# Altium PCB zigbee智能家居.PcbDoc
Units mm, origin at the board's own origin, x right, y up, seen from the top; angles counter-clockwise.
Board outline 97 x 70 mm, 2 copper layers (Top Layer, Bottom Layer); 56 components, 64 nets, 275 pads, 46 vias.
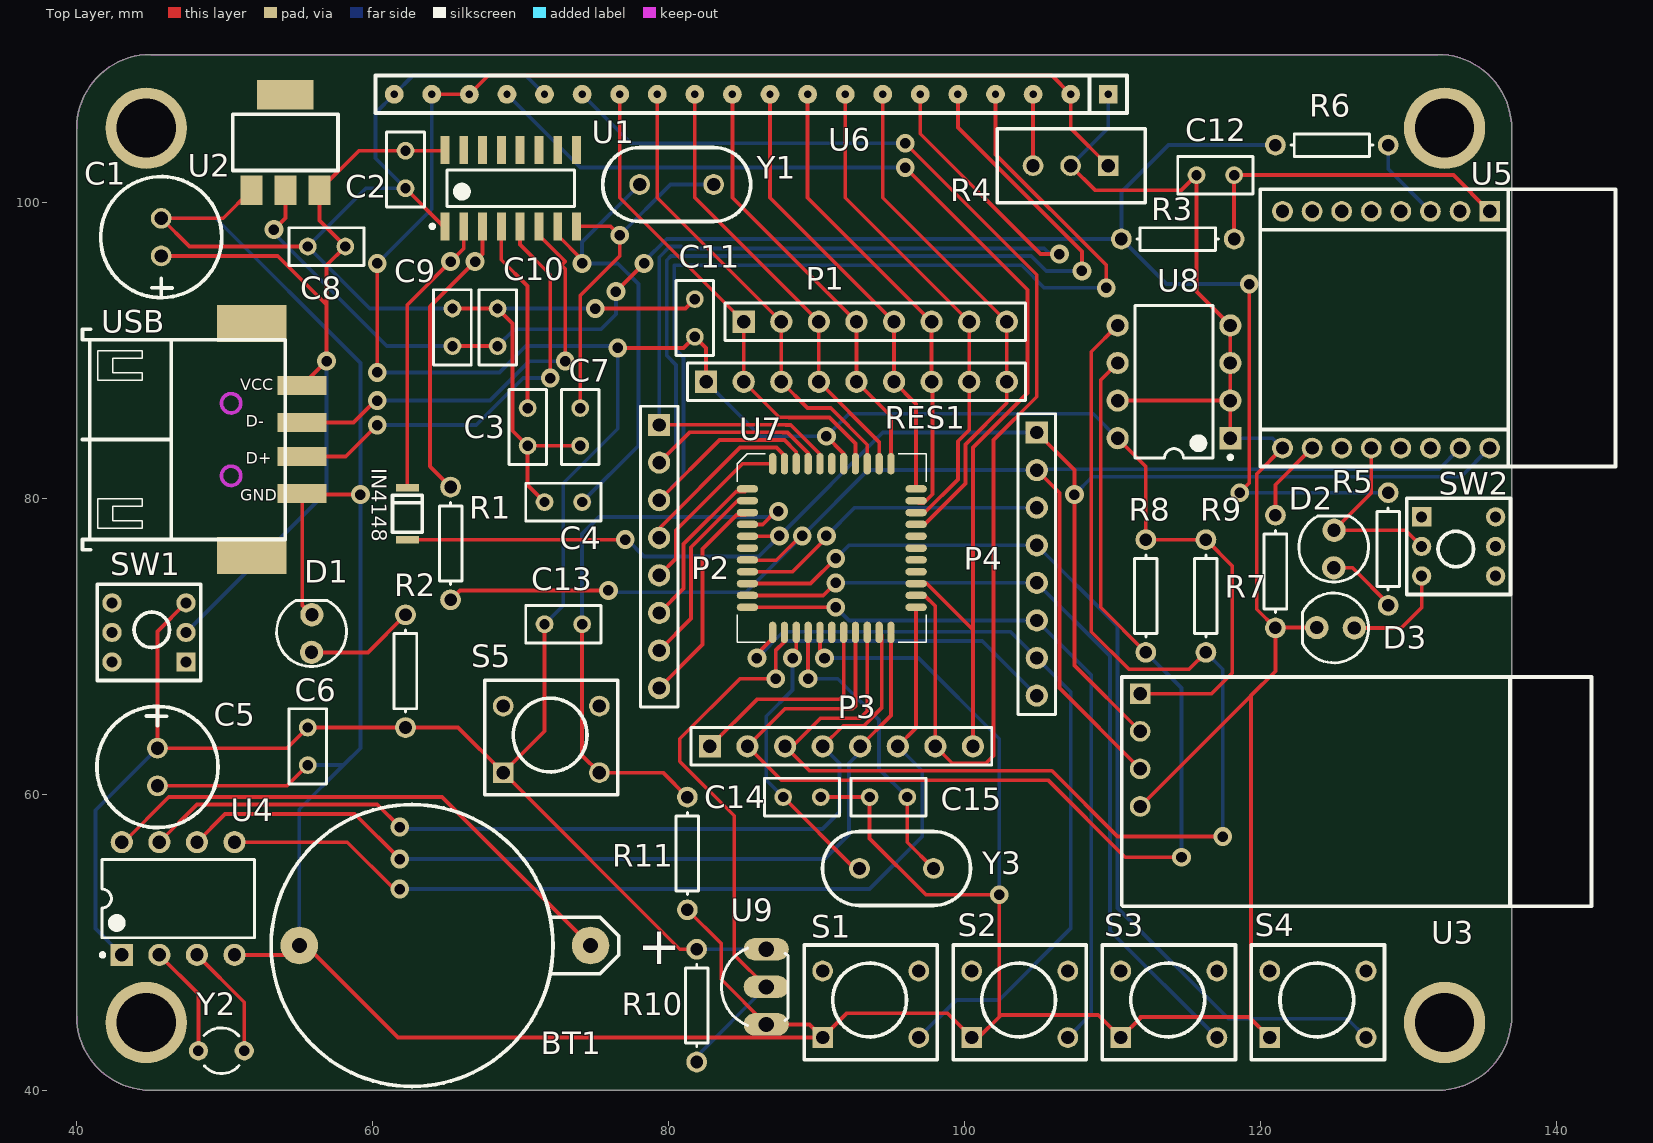
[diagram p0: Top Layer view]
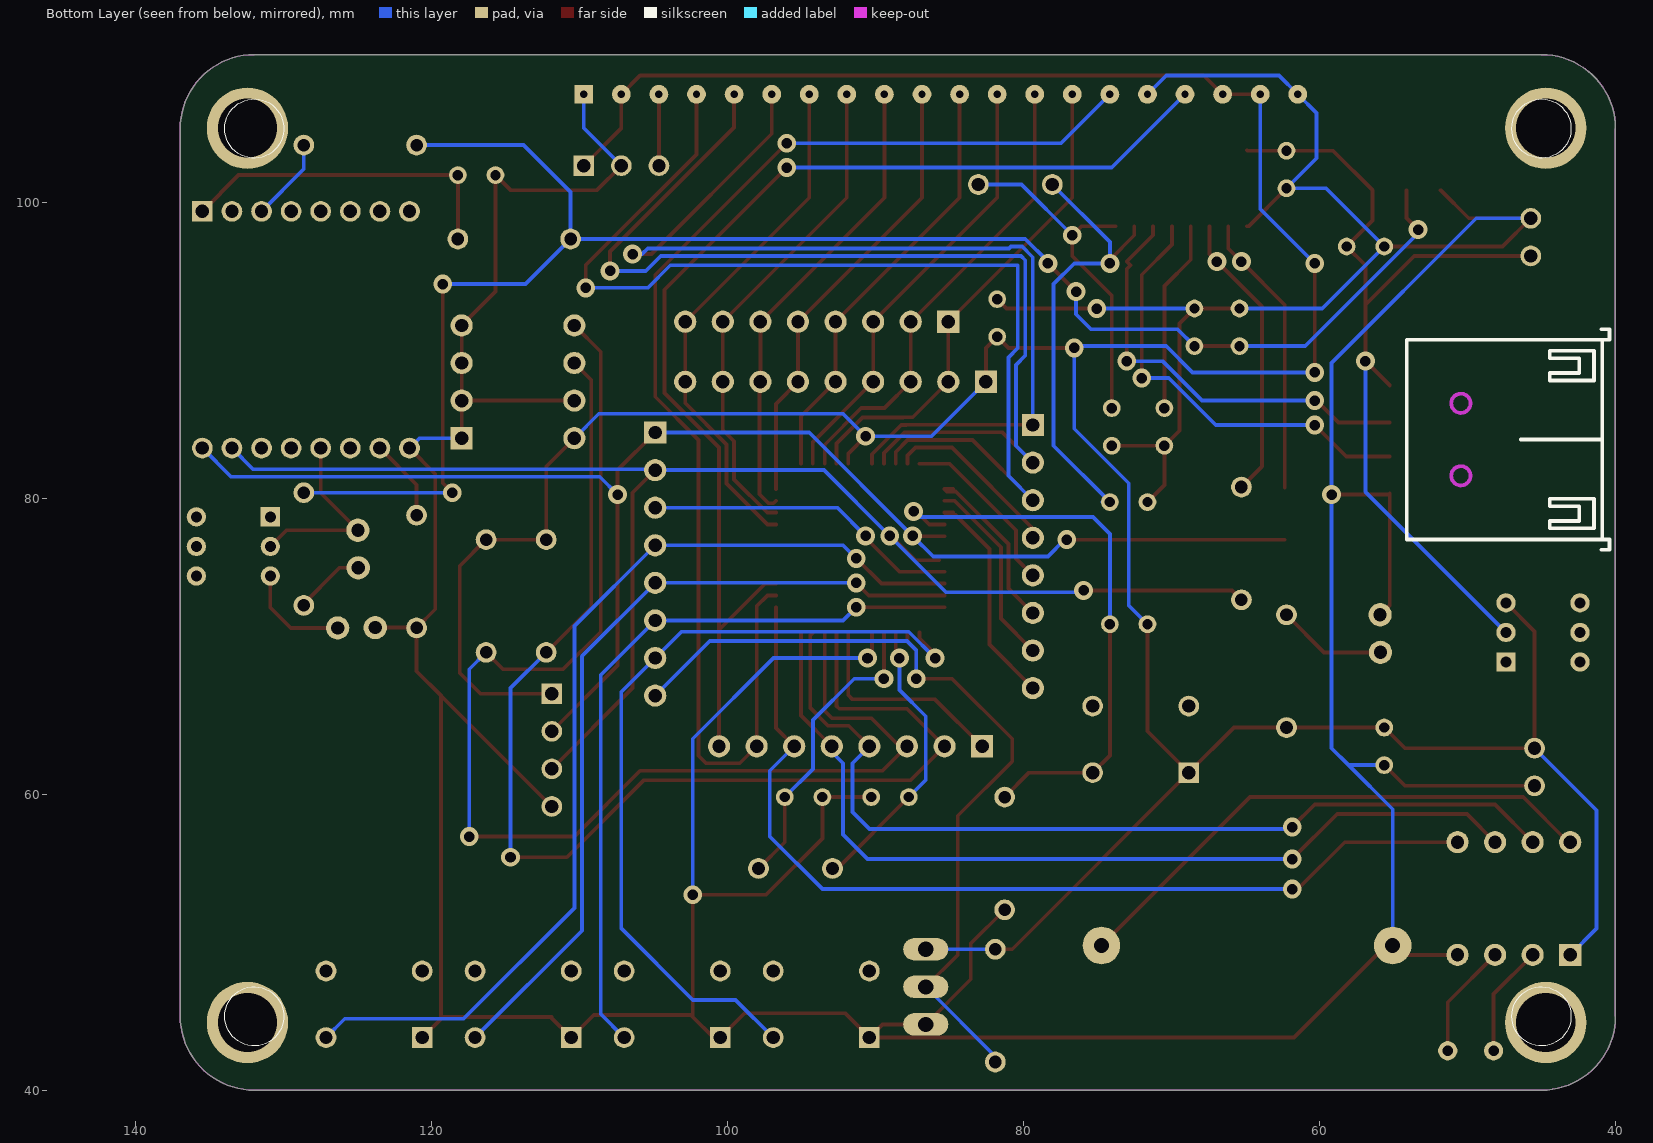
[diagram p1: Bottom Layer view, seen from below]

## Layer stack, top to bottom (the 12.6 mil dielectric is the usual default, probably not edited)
Top Solder: solder mask 0.0102, Solder Resist, Dk 3.5
Top Layer: signal copper 0.0356
Dielectric 1: dielectric 0.32, FR-4, Dk 4.8
Bottom Layer: signal copper 0.0356
Bottom Solder: solder mask 0.0102, Solder Resist, Dk 3.5

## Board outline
40,45 40,105 cw(c45,105) 45,110 132,110 cw(c132,105) 137,105 137,45 cw(c132,45) 132,40 45,40 cw(c45,45)

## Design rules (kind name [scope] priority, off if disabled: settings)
Clearance [All] p1: gap=0.254
HoleSize [All] p1 off: absolutevalues=TRUE maxlimit=2.54 minlimit=0.025 maxpercent=80.000 minpercent=20.000
MinimumSolderMaskSliver MinimumSolderMaskSliver_1 [All] p1: minsoldermaskwidth=0
PolygonConnect [All] p1: connectstyle=Relief reliefconductorwidth=0.254 reliefentries=4 polygonreliefangle="90 Angle" airgapwidth=0.254
RoutingVias [All] p1: holewidth=0.711 width=1.27 viastyle="Through Hole" minholewidth=0.711 minwidth=1.27 maxholewidth=0.711 maxwidth=1.27
SilkToSilkClearance [All] p1 off: silktosilkclearance=0.254
SilkToSolderMaskClearance [IsPad] p1 off: minsilkscreentomaskgap=0.1 clearancetoexposedcopper=TRUE
SolderMaskExpansion [All] p1: expansion=0.102
Width [All] p1: maxlimit=0.254 minlimit=0.254 preferedwidth=0.254
26 further rules are at their usual default settings.

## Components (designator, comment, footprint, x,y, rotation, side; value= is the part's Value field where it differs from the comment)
BT1 "Battery" BATTERY 64.897,49.784 r180 top
C1 "Cap Pol1" "8mm Cap+" 45.974,110.363 r270 top
C2 "Cap" RAD-0.1 62.23,102.235 r90 top
C3 "Cap" RAD-0.1 70.485,84.836 r90 top
C4 "Cap" RAD-0.1 72.898,79.756 r0 top
C5 "Cap Pol1" "8mm Cap+" 45.212,49.149 r90 top
C6 "Cap" RAD-0.1 55.626,63.246 r90 top
C7 "Cap" RAD-0.1 74.041,84.836 r90 top
C8 "Cap" RAD-0.1 56.896,97.028 r180 top
C9 "Cap" RAD-0.1 65.405,91.567 r90 top
C10 "Cap" RAD-0.1 68.453,91.567 r90 top
C11 "Cap" RAD-0.1 81.788,92.202 r90 top
C12 "Cap" RAD-0.1 116.967,101.854 r180 top
C13 "Cap" RAD-0.1 72.898,71.501 r180 top
C14 "Cap" RAD-0.1 94.869,59.817 r0 top
C15 "Cap" RAD-0.1 89.027,59.817 r180 top
D1 "LED3" LED 55.88,72.136 r270 top
D2 "LED3" LED 124.968,77.851 r270 top
D3 "LED3" LED 123.825,71.247 r0 top
IN4148 "IN4148" LL-34 62.357,77.216 r90 top
P1 "Header 8" HDR1X8 85.09,91.948 r0 top
P2 "Header 8" HDR1X8 79.375,84.963 r270 top
P3 "Header 8" HDR1X8 82.804,63.246 r0 top
P4 "Header 8" HDR1X8 104.902,84.455 r270 top
R1 "Res1" AXIAL-0.3 65.278,76.962 r90 top
R2 "Res1" AXIAL-0.3 62.23,68.326 r90 top
R3 "Res1" AXIAL-0.3 114.427,97.536 r180 top
R4 "Res Tap" 变位器 109.728,102.489 r180 top
R5 "Res1" AXIAL-0.3 128.651,76.581 r90 top
R6 "Res1" AXIAL-0.3 124.841,103.886 r0 top
R7 "Res1" AXIAL-0.3 121.031,75.057 r270 top
R8 "Res1" AXIAL-0.3 112.268,73.406 r90 top
R9 "Res1" AXIAL-0.3 116.332,73.406 r90 top
R10 "Res1" AXIAL-0.3 81.915,45.72 r90 top
R11 "Res1" AXIAL-0.3 81.28,56.007 r90 top
RES1 "10K" HDR1X9 82.55,87.884 r0 top
S1 "SW-PB" 6x6四脚开关 90.424,43.561 r0 top
S2 "SW-PB" 6x6四脚开关 100.499,43.561 r0 top
S3 "SW-PB" 6x6四脚开关 110.575,43.561 r0 top
S4 "SW-PB" 6x6四脚开关 120.65,43.561 r0 top
S5 "SW-PB" 6x6四脚开关 68.834,61.468 r0 top
SW1 "Component_1" 6x6六脚开关 48.895,67.945 r90 top
SW2 "Component_1" 6x6六脚开关 129.413,79.756 r270 top
U1 "CH340G" SOIC127P600X170-16N 69.342,100.965 r90 top
U2 "AMS1117-3V3" SOT223 51.816,100.838 r0 top
U3 "ZIGBEE" zigbee直插 111.887,59.182 r0 top
U4 "DS1302" DIP-8 46.863,52.959 r90 top
U5 "ESP-12" ESP-12 127.508,97.155 r180 top
U6 "QC12864B" SIP20 109.728,107.315 r180 top
U7 "STC12C5A60S2" LQFP44 85.344,80.645 r0 top
U8 "24C08A" dip-8 114.173,87.884 r180 top
U9 "DS18B20" TO92 86.614,46.99 r90 top
USB "USB" USB-4-A-SMT 55.245,87.63 r0 top (schematic designator *1)
Y1 "12M" 5mm晶振 83.058,101.219 r180 top
Y2 "37.128KHz" R38 49.784,42.672 r90 top
Y3 "12M" 5mm晶振 97.917,54.991 r180 top

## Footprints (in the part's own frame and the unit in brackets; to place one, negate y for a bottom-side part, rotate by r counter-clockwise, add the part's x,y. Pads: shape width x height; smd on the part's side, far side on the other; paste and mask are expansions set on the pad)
5mm晶振 [mm]
  round 1.4 hole 0.9: 1(0,0) 2(5,0)
  silkscreen extent -2.5,-2.5 7.5,2.5
6x6六脚开关 [mm]
  rect 1.3x1.3 hole 0.75: 1(1,1.5)
  round 1.3 hole 0.75: 2(3,1.5) 3(5,1.5) 4(1,6.5) 5(3,6.5) 6(5,6.5)
  silkscreen extent -0.25,0.5 6.25,7.5
6x6四脚开关 [mm]
  rect 1.4x1.4 hole 0.9 paste+4.5: 1(0,0)
  round 1.4 hole 0.9: 2(6.5,0) 3(6.5,4.5) 4(0,4.5)
  silkscreen extent -1.25,-1.5 7.75,6.25
"8mm Cap+" [mm]
  round 1.4 hole 0.9: 1(13.97,-0.254) 2(11.43,-0.254)
  silkscreen extent 8.61,-4.35 16.8,3.84
AXIAL-0.3 [mm] "Axial Device, Thru-Hole; 2 Leads; 0.3 in Pin Spacing"
  round 1.4 hole 0.85: 1(-3.81,0) 2(3.81,0)
  silkscreen extent -2.77,-0.76 2.77,0.76
BATTERY [mil]
  round 100 hole 40: 1(-387.5,0) 2(387.5,0)
  silkscreen extent -462,-375 462,375
DIP-8 [mm] "DIP; 8 Leads; Row Spacing 7.62 mm; Pitch 2.54 mm"
  rect 1.5x1.5 hole 0.9: 1(-3.81,3.81)
  round 1.5 hole 0.9: 2(-3.81,1.27) 3(-3.81,-1.27) 4(-3.81,-3.81) 5(3.81,-3.81) 6(3.81,-1.27) 7(3.81,1.27) 8(3.81,3.81)
  silkscreen extent -3.93,-5.15 2.65,5.23, body extent -3.6,-5.15 3.6,5.15, height 5.08
dip-8 [mm] "DIP; 8 Leads; Row Spacing 7.62 mm; Pitch 2.54 mm"
  rect 1.5x1.5 hole 0.9: 1(-3.81,3.81)
  round 1.5 hole 0.9: 2(-3.81,1.27) 3(-3.81,-1.27) 4(-3.81,-3.81) 5(3.81,-3.81) 6(3.81,-1.27) 7(3.81,1.27) 8(3.81,3.81)
  silkscreen extent -3.94,-5.15 2.65,5.23, body extent -3.6,-5.15 3.6,5.15, height 5.08
ESP-12 [mm]
  rect 1.4x1.4 hole 0.9: 1(-8,-2.25)
  round 1.4 hole 0.9: 2(-6,-2.25) 3(-4,-2.25) 4(-2,-2.25) 5(0,-2.25) 6(2,-2.25) 7(4,-2.25) 8(6,-2.25) 9(6,13.75) 10(4,13.75) 11(2,13.75) 12(0,13.75) 13(-2,13.75) 14(-4,13.75) 15(-6,13.75) 16(-8,13.75)
  silkscreen extent -16.5,-3.75 7.5,15
HDR1X8 [mm] "Connector; Header; 8 Position"
  rect 1.5x1.5 hole 0.9: 1(0,0)
  round 1.5 hole 0.9: 2(2.54,0) 3(5.08,0) 4(7.62,0) 5(10.16,0) 6(12.7,0) 7(15.24,0) 8(17.78,0)
  silkscreen extent -1.27,-1.27 19.05,1.27
HDR1X9 [mm] "Connector; Header; 9 Position"
  rect 1.5x1.5 hole 0.9: 1(0,0)
  round 1.5 hole 0.9: 2(2.54,0) 3(5.08,0) 4(7.62,0) 5(10.16,0) 6(12.7,0) 7(15.24,0) 8(17.78,0) 9(20.32,0)
  silkscreen extent -1.27,-1.27 21.59,1.27
LED [mil]
  round 62 hole 35.43: 1(100,0) 2(0,1)
  silkscreen extent -38,-93 138,93
LL-34 [mm]
  rect 0.5x1.54 smd: 1(0,0) 2(3.5,0)
  silkscreen extent 0.5,-1 3,1
LQFP44 [mm]
  oval 1.45x0.5 smd: 1(0,0) 2(0,-0.8) 3(0,-1.6) 4(0,-2.4) 5(0,-3.2) 6(0,-4) 7(0,-4.8) 8(0,-5.6) 9(0,-6.4) 10(0,-7.2) 11(0,-8) 23(11.4,-8) 24(11.4,-7.2) 25(11.4,-6.4) 26(11.4,-5.6) 27(11.4,-4.8) 28(11.4,-4) 29(11.4,-3.2) 30(11.4,-2.4) 31(11.4,-1.6) 32(11.4,-0.8) 33(11.4,0)
  oval 0.5x1.45 smd: 12(1.7,-9.7) 13(2.5,-9.7) 14(3.3,-9.7) 15(4.1,-9.7) 16(4.9,-9.7) 17(5.7,-9.7) 18(6.5,-9.7) 19(7.3,-9.7) 20(8.1,-9.7) 21(8.9,-9.7) 22(9.7,-9.7) 34(9.7,1.7) 35(8.9,1.7) 36(8.1,1.7) 37(7.3,1.7) 38(6.5,1.7) 39(5.7,1.7) 40(4.9,1.7) 41(4.1,1.7) 42(3.3,1.7) 43(2.5,1.7) 44(1.7,1.7)
  silkscreen extent -0.67,-10.38 12.08,2.37
R38 [mm] "Crystal, Thru-Hole; 2 Leads; Body 3.1 x 8.2 mm (Dia.xH)"
  round 1.3 hole 0.7: 1(0,1.55) 2(0,-1.55)
  silkscreen extent -1.55,-1.19 1.55,1.17
RAD-0.1 [mm] "Radial Cap, Thru-Hole; 2 Leads; 0.1 in Pin Spacing"
  round 1.2 hole 0.7: 1(-1.27,0) 2(1.27,0)
  silkscreen extent -2.54,-1.27 2.54,1.27
SIP20 [mm]
  rect 1.27x1.27 hole 0.5: 1(0,0)
  round 1.27 hole 0.5: 2(2.54,0) 3(5.08,0) 4(7.62,0) 5(10.16,0) 6(12.7,0) 7(15.24,0) 8(17.78,0) 9(20.32,0) 10(22.86,0) 11(25.4,0) 12(27.94,0) 13(30.48,0) 14(33.02,0) 15(35.56,0) 16(38.1,0) 17(40.64,0) 18(43.18,0) 19(45.72,0) 20(48.26,0)
  silkscreen extent -1.27,-1.27 49.53,1.27
SOIC127P600X170-16N [mm] "SOIC, 16-Leads, Body 8.6x4.0mm (max), Pitch 1.27mm, IPC Medium Density"
  rect 1.9x0.6 smd: 1(-2.575,4.445) 2(-2.575,3.175) 3(-2.575,1.905) 4(-2.575,0.635) 5(-2.575,-0.635) 6(-2.575,-1.905) 7(-2.575,-3.175) 8(-2.575,-4.445) 9(2.575,-4.445) 10(2.575,-3.175) 11(2.575,-1.905) 12(2.575,-0.635) 13(2.575,0.635) 14(2.575,1.905) 15(2.575,3.175) 16(2.575,4.445)
  silkscreen extent -2.7,-4.3 1.22,5.42, body extent -1.98,-4.28 1.97,4.28, height 1.7
SOT223 [mil]
  rect 59x79 smd: 1(0,0) 2(90.55,0) 3(181.1,0)
  rect 150x79 smd: 4(89.88,253.54)
  silkscreen extent -49,52 231,202
TO92 [mil]
  oval 60x120 hole 40: 1(-100,0) 2(0,0) 3(100,0)
  silkscreen extent -103,-58 103,119
USB-4-A-SMT [mm]
  rect 3.3x1.3 smd: 1(0,0) 2(0,-2.5) 3(0,-4.8) 4(0,-7.3)
  rect 4.7x2.5 smd: 5(-3.4,-11.5) 6(-3.4,4.2)
  Keep-Out Layer circle w0.254: c-4.8,-1.2 r0.65
  Keep-Out Layer circle w0.254: c-4.8,-6.1 r0.65
  silkscreen extent -14.85,-11.1 -1.15,3.8
zigbee直插 [mm]
  rect 1.4x1.4 hole 0.9: 1(0,7.62)
  round 1.4 hole 0.9: 2(0,5.08) 3(0,2.54) 4(0,0)
  silkscreen extent -1.25,-6.75 30.5,8.75
变位器 [mm]
  rect 1.4x1.4 hole 0.9: 1(0,0)
  round 1.4 hole 0.9: 2(2.54,0) 3(5.08,0)
  silkscreen extent -2.5,-2.5 7.5,2.5

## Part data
BT1: "Multicell Battery"
C1 C5: "Polarized Capacitor (Radial)"
C2 C3 C4 C6 C7 C8 C9 C10 C11 C12 C13 C14 C15: "Capacitor"
D1 D2 D3: "Typical BLUE SiC LED"
IN4148: library part 4148
P1 P2 P3 P4: "Header, 8-Pin"
R1 R2 R3 R5 R6 R7 R8 R9 R10 R11: "Resistor"
R4: "Tapped Resistor"
RES1: library part "Header 9", "Header, 9-Pin"
S1 S2 S3 S4 S5: "Switch"
U1 U2 U5: library part Component_1
U3: library part "Header 4", "Header, 4-Pin"
U6: library part FM12864M
U8: library part 24C64
USB: library part COMPONENT_1
Y1 Y3: library part XTAL
Y2: library part XTAL, "Crystal Oscillator"

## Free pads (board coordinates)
  round 5.5 hole 4: 0(44.704,105.029) 1(132.461,105.029) 2(132.461,44.577) 3(44.704,44.577)

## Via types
v1: diameter 1.27, hole 0.711, Top Layer to Bottom Layer, 46 vias

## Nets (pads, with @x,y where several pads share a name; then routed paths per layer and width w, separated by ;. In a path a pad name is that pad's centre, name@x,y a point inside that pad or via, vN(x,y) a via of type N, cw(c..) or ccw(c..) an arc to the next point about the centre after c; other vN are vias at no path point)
D+: U1.5 USB.3 | length 30.3
  Top Layer w0.254: USB.3 58.192,82.83 v1(60.325,84.963) v1@60.325,84.709 ; U1.5 69.977,97.155 72.009,95.123 v1(72.009,88.138)
  Bottom Layer w0.254: v1(60.325,84.963) 67.012,84.963 70.187,88.138 v1(72.009,88.138)
D-: U1.6 USB.2 | length 29.6
  Top Layer w0.254: USB.2 58.714,85.13 60.198,86.614 v1(60.325,86.614) ; U1.6 71.247,97.79 73.025,96.012 72.771,95.758 73.025,95.504 v1(73.025,89.281)
  Bottom Layer w0.254: v1(60.325,86.614) 67.945,86.614 70.612,89.281 v1(73.025,89.281)
GND: BT1.2 C1.2 C2.1 C3.1 C4.1 C5.2 C6.1 C7.1 C8.2 C9.2 C10.2 C11.2 C12.2 C14.1 C15.1 D1.2 D3.2 R4.2 R7.2 R11.1 S1.1 S2.1 S3.1 S4.1 U1.1 U2.1 U3.4 U4.4 U5.9 U6.1 U6.16 U6.20 U7.16 U8.1 U8.2 U8.3 U8.4 U8.7 U9.1 USB.4 | length 424.3
  Top Layer w0.254: C5.2 54.229,60.579 C6.1 ; U4.4 54.419,49.149 BT1.2 55.499,49.784 61.722,43.561 S1.1 ; U2.1 49.911,98.933 C1.2 47.625,97.028 C8.2 ; USB.4 55.245,72.796 D1.2 ; USB.4@55.311,80.264 v1(59.182,80.264) ; C2.1 64.805,98.39 U1.1 ; C9.2 C10.2 69.469,91.821 69.469,84.582 C3.1 ; C4.1 70.485,80.899 C3.1 ; C7.1 C3.1 ; v1(75.057,92.837) 81.153,92.837 C11.2 ; R11.1 83.566,49.911 83.566,47.498 U9.1 89.535,44.45 S1.1 ; U7.16 90.244,69.776 90.551,69.469 v1(90.551,69.215) ; C15.1 C14.1 93.599,57.023 97.409,53.213 v1(102.362,53.213) 102.362,44.958 ; R4.2 108.839,100.838 114.681,100.838 C12.2 115.697,93.98 U8.4 U8.3 U8.2 ; U8.7 U8.2 ; U3.4 121.031,68.326 ; U8.1 U8.2 ; U5.9 119.761,81.658 119.761,72.517 R7.2 ; D3.2 121.056,71.272 R7.2 ; S1.1 92.075,45.212 98.848,45.212 S2.1 100.965,43.561 102.362,44.958 ; 102.362,44.958 102.489,45.085 109.051,45.085 S3.1 111.972,44.958 119.253,44.958 S4.1 119.38,44.831 119.38,66.675 121.031,68.326 ; 121.031,68.326 R7.2
  Bottom Layer w0.254: C1.2 49.403,98.933 59.182,89.154 v1(59.182,80.264) 59.182,63.119 58.039,61.976 ; BT1.2 55.054,58.991 58.039,61.976 ; C6.1 58.039,61.976 ; C9.2 59.817,92.837 C8.2 59.563,100.965 C2.1 60.198,102.997 60.198,106.045 U6.20 62.738,108.585 70.358,108.585 U6.16 ; C10.2 v1(75.057,92.837) ; v1(90.551,69.215) 96.901,69.215 102.362,63.754 v1(102.362,53.213) ; R4.2 109.728,105.029 U6.1 ; U8.1 120.839,84.074 U5.9
NetBT1_1: BT1.1 U4.8 | length 37.1
  Top Layer w0.254: U4.8 43.185,56.769 46.233,59.817 64.706,59.817 BT1.1
NetC3_2: C3.2 U1.4 | length 13
  Top Layer w0.254: U1.4 68.707,96.139 70.485,94.361 C3.2
NetC4_2: C4.2 U1.7 Y1.2 | length 31.3
  Top Layer w0.254: U1.7 72.517,97.79 74.168,96.139 v1(74.168,95.885)
  Bottom Layer w0.254: C4.2@74.676,79.756 C4.2 77.978,83.566 77.978,94.488 76.581,95.885 v1(74.168,95.885) 74.168,97.329 Y1.2
NetC7_2: C7.2 U1.8 Y1.1 | length 23.7
  Top Layer w0.254: U1.8 76.108,98.39 v1(76.708,97.79) 76.708,96.393 74.041,93.726 C7.2
  Bottom Layer w0.254: v1(76.708,97.79) 80.137,101.219 Y1.1
NetC12_1: C12.1 R3.1 U5.1 | length 22.6
  Top Layer w0.254: R3.1 C12.1 133.059,101.854 U5.1
NetD1_1: D1.1 R2.2 | length 7.4
  Top Layer w0.254: D1.1 59.69,69.596 R2.2
NetD2_1: D2.1 R5.1 | length 4.9
  Top Layer w0.254: D2.1 126.238,75.311 R5.1@128.778,72.771
NetD2_2: D2.2 SW2.2 U5.12 | length 13
  Top Layer w0.254: U5.12 127.508,80.366 D2.2 129.818,77.851 SW2.2
NetD3_1: D3.1 SW2.3 | length 7.3
  Top Layer w0.254: D3.1 129.54,71.247 130.913,72.62 SW2.3
NetIN4148_2: IN4148.2 U1.2 | length 19.3
  Top Layer w0.254: IN4148.2 62.357,93.091 v1(65.278,96.012) 66.167,96.901 U1.2
NetR1_2: R1.2 U1.3 | length 19.7
  Top Layer w0.254: R1.2 63.881,82.169 63.881,92.964 v1(66.929,96.012) 67.437,96.52 U1.3
NetR4_3: R4.3 U6.3 | length 4.8
  Top Layer w0.254: R4.3 U6.3
NetR6_2: R6.2 U5.3 | length 5.7
  Bottom Layer w0.254: R6.2 128.651,102.262 U5.3
NetR7_1: R7.1 U5.10 | length 5.6
  Top Layer w0.254: R7.1 121.031,80.928 U5.10
NetU4_2: U4.2 Y2.1 | length 7.6
  Top Layer w0.254: U4.2 48.234,46.508 Y2.1
NetU4_3: U4.3 Y2.2 | length 7.8
  Top Layer w0.254: U4.3 51.334,45.948 Y2.2
P00: P1.1 RES1.2 U6.14 U7.37 | length 33.6
  Top Layer w0.254: U6.14 76.708,100.33 P1.1 RES1.2 87.491,85.483 88.147,85.483 88.159,85.471 90.888,85.471 92.644,83.715 U7.37
P01: P1.2 RES1.3 U6.13 U7.36 | length 31.8
  Top Layer w0.254: U6.13 79.248,100.33 P1.2 RES1.3 89.408,86.106 90.972,86.106 93.444,83.634 U7.36
P02: P1.3 RES1.4 U6.12 U7.35 | length 30.1
  Top Layer w0.254: U6.12 81.788,100.33 P1.3 RES1.4 94.244,83.81 U7.35
P03: P1.4 RES1.5 U6.11 U7.34 | length 29.4
  Top Layer w0.254: U6.11 84.328,100.33 P1.4 RES1.5 95.044,85.55 U7.34
P04: P1.5 RES1.6 U6.10 U7.33 | length 30.8
  Top Layer w0.254: U6.10 86.868,100.33 P1.5 RES1.6 96.744,86.39 U7.33
P05: P1.6 RES1.7 U6.9 U7.32 | length 32
  Top Layer w0.254: U6.9 89.408,100.33 P1.6 RES1.7 97.85,87.824 97.85,80.28 97.246,79.676 96.913,79.676 U7.32
P06: P1.7 RES1.8 U6.8 U7.31 | length 33.6
  Top Layer w0.254: U6.8 91.948,100.33 P1.7 RES1.8 100.33,84.622 99.568,83.86 99.568,81.28 97.333,79.045 U7.31
P07: P1.8 RES1.9 U6.7 U7.30 | length 35.4
  Top Layer w0.254: U6.7 94.488,100.33 P1.8 RES1.9 102.87,86.443 100.076,83.649 100.076,81.01 97.311,78.245 U7.30
P10: P2.1 U6.6 U7.40 | length 66.7
  Top Layer w0.254: P2.1 79.387,84.975 87.937,84.975 87.949,84.963 88.265,84.963 90.244,82.984 U7.40 ; U6.6 97.028,104.648 105.156,96.52 v1(106.426,96.52)
  Bottom Layer w0.254: P2.1 79.375,96.306 80.097,97.028 80.855,97.028 80.982,96.901 105.41,96.901 105.791,96.52 v1(106.426,96.52)
P11: P2.2 U6.5 U7.41 | length 70.6
  Top Layer w0.254: P2.2 81.419,84.467 87.726,84.467 87.738,84.455 88.055,84.455 89.444,83.066 U7.41 ; U6.5 99.568,105.073 107.95,96.691 v1(107.95,95.377)
  Bottom Layer w0.254: P2.2 80.518,83.566 80.518,89.027 79.883,89.662 79.883,96.095 80.181,96.393 104.521,96.393 105.537,95.377 v1(107.95,95.377)
P12: P2.3 U6.4 U7.42 | length 74.9
  Top Layer w0.254: P2.3 83.451,83.959 87.516,83.959 87.528,83.947 87.844,83.947 88.644,83.147 U7.42 ; U6.4 102.108,103.251 109.601,95.758 v1(109.601,94.234)
  Bottom Layer w0.254: P2.3 81.026,81.534 81.026,89.535 80.391,90.17 80.391,95.758 103.886,95.758 105.41,94.234 v1(109.601,94.234)
P13: P2.4 U7.43 | length 12.2
  Top Layer w0.254: P2.4 79.375,77.978 84.848,83.451 87.305,83.451 87.844,82.912 U7.43
P14: P2.5 U7.44 | length 11.9
  Top Layer w0.254: P2.5 80.518,75.946 80.518,77.851 85.012,82.345 U7.44
P15: P2.6 U7.1 | length 11.8
  Top Layer w0.254: P2.6 81.026,73.914 81.026,76.918 84.584,80.476 85.175,80.476 U7.1 U7.1@84.777,80.645
P16: P2.7 U7.2 | length 13
  Top Layer w0.254: P2.7 81.534,71.882 81.534,76.708 84.671,79.845 U7.2
P17: P2.8 U7.3 | length 15.2
  Top Layer w0.254: P2.8 82.313,70.121 82.313,76.581 84.608,78.876 85.175,78.876 U7.3 U7.3@84.777,79.045
P20: P3.1 U7.18 | length 14.7
  Top Layer w0.254: P3.1 85.979,66.421 91.567,66.421 91.844,66.698 U7.18
P21: P3.2 R8.1 U7.19 U8.6 | length 82
  Top Layer w0.254: U7.19 92.644,65.974 92.456,65.786 87.884,65.786 P3.2 87.63,60.96 105.664,60.96 110.871,55.753 v1(114.681,55.753) ; U8.6 109.22,88.011 109.22,72.644 R8.1
  Bottom Layer w0.254: R8.1 114.681,67.183 v1(114.681,55.753)
P22: P3.3 R9.1 U7.20 U8.5 | length 87.6
  Top Layer w0.254: U7.20 93.444,65.631 92.964,65.151 90.297,65.151 88.392,63.246 P3.3 89.535,61.595 105.918,61.595 110.363,57.15 v1(117.475,57.15) ; U8.5 108.585,89.916 108.585,70.993 111.125,68.453 115.189,68.453 R9.1
  Bottom Layer w0.254: R9.1 117.475,68.453 v1(117.475,57.15)
P23: P3.4 U4.7 U7.21 | length 63.3
  Top Layer w0.254: U4.7 48.133,59.309 60.325,59.309 v1(61.849,57.785) ; P3.4 91.821,64.643 93.218,64.643 94.413,65.838 94.413,70.776 U7.21
  Bottom Layer w0.254: v1@61.849,57.658 90.424,57.658 91.567,58.801 91.567,62.103 P3.4
P24: P3.5 U4.6 U7.22 | length 61.6
  Top Layer w0.254: U4.6 50.038,58.674 58.801,58.674 v1(61.849,55.626) ; P3.5 95.044,65.326 U7.22
  Bottom Layer w0.254: v1(61.849,55.626) 90.551,55.626 92.202,57.277 92.202,62.103 92.964,62.865 P3.5
P25: P3.6 U4.5 U7.23 | length 66
  Top Layer w0.254: U4.5 58.293,56.769 61.468,53.594 v1(61.849,53.594) ; P3.6 96.744,64.486 U7.23
  Bottom Layer w0.254: v1(61.849,53.594) 93.599,53.594 97.155,57.15 97.155,61.595 P3.6
P26: P3.7 U6.15 U7.24 | length 85.2
  Top Layer w0.254: v1(96.012,104.013) 104.902,95.123 104.902,86.868 101.981,83.947 101.981,62.611 101.473,62.103 99.187,62.103 P3.7 98.044,72.712 97.311,73.445 U7.24
  Bottom Layer w0.254: U6.15 77.47,104.013 v1(96.012,104.013)
P27: P3.8 U6.17 U7.25 | length 78.2
  Top Layer w0.254: v1(96.012,102.362) 104.267,94.107 104.267,87.122 100.584,83.439 P3.8 ; U7.25 97.459,74.245 100.584,71.12
  Bottom Layer w0.254: U6.17 74.041,102.362 v1(96.012,102.362)
P30: IN4148.1 P4.1 U3.2 U5.16 U7.5 | length 101.1
  Top Layer w0.254: IN4148.1 v1(77.089,77.216) ; U7.5 87.478,77.445 v1(87.503,77.47) ; P4.1 107.442,81.915 v1(107.442,80.264) 107.442,68.707 U3.2
  Bottom Layer w0.254: v1(77.089,77.216) 77.216,77.216 78.359,76.073 86.106,76.073 v1(87.503,77.47) 94.488,84.455 P4.1 ; v1(107.442,80.264) 108.65,81.472 133.575,81.472 U5.16
P31: P4.2 R1.1 U3.3 U5.15 U7.7 | length 99.7
  Top Layer w0.254: R1.1 65.913,73.787 v1(75.946,73.787) ; U7.7@85.708,75.819 87.289,75.819 88.94,77.47 v1(89.047,77.47) ; P4.2 106.426,80.391 106.426,67.183 U3.3
  Bottom Layer w0.254: v1(75.946,73.787) 76.073,73.66 85.237,73.66 v1(89.047,77.47) 93.492,81.915 P4.2 104.967,81.98 132.083,81.98 U5.15
P32: P4.3 U7.8 | length 21.4
  Top Layer w0.254: U7.8 88.38,75.045 90.678,77.343 v1(90.678,77.47)
  Bottom Layer w0.254: v1(90.678,77.47) 92.583,79.375 P4.3
P33: P4.4 S4.2 U7.9 | length 67.8
  Top Layer w0.254: U7.9 89.612,74.245 v1(91.313,75.946)
  Bottom Layer w0.254: v1(91.313,75.946) 92.202,76.835 P4.4 110.363,71.374 110.363,52.324 117.856,44.831 125.88,44.831 S4.2
P34: P4.5 S3.2 U7.10 | length 55.7
  Top Layer w0.254: U7.10 90.463,73.445 v1(91.313,74.295)
  Bottom Layer w0.254: v1(91.313,74.295) P4.5 109.855,69.342 109.855,50.781 S3.2
P35: P4.6 S2.2 U7.11 | length 50.3
  Top Layer w0.254: U7.11 v1(91.312,72.645) v1(91.312,72.645)
  Bottom Layer w0.254: v1(91.312,72.645) 92.202,71.755 P4.6 108.585,68.072 108.585,45.147 S2.2
P36: P4.7 S1.2 U7.12 | length 55.2
  Top Layer w0.254: v1@85.725,69.215 87.044,70.534 U7.12
  Bottom Layer w0.254: v1(85.979,69.215) 87.757,70.993 103.124,70.993 P4.7 107.188,66.929 107.188,50.927 102.362,46.101 99.464,46.101 S1.2
P37: P4.8 R10.1 U7.13 U9.2 | length 59.1
  Top Layer w0.254: U9.2 84.455,49.149 84.455,58.547 80.772,62.23 80.772,63.754 84.836,67.818 v1(87.249,67.818) 87.249,69.723 87.844,70.318 U7.13
  Bottom Layer w0.254: R10.1 81.915,42.291 U9.2 ; v1(87.249,67.818) 87.249,69.723 87.884,70.358 101.219,70.358 P4.8
P40: U7.17
P41: U7.28
P42: U7.39
P43: U7.6
P44: U7.26
P45: U7.27
P46: U7.29
RST: C13.1 R11.2 S5.2 U7.4 | length 39.6
  Top Layer w0.254: C13.1 74.168,62.634 S5.2 79.629,61.468 R11.2 ; U7.4 86.373,78.245 87.249,79.121 v1(87.439,79.121)
  Bottom Layer w0.254: C13.1 74.168,77.597 75.311,78.74 87.058,78.74 v1(87.439,79.121)
VCC_3V3: C9.1 C10.1 R3.2 R5.2 R6.1 U2.2 | length 116.8
  Top Layer w0.254: v1(53.34,98.171) 54.116,98.947 U2.2 ; C9.1 C10.1 ; v1(76.454,93.98) v1(78.359,95.885) ; v1(118.618,80.391) 119.253,81.026 v1(119.253,94.488)
  Bottom Layer w0.254: v1(53.34,98.171) 53.34,97.927 60.97,90.297 C9.1 ; C10.1 69.596,91.44 75.438,91.44 76.454,92.456 v1(76.454,93.98) ; v1(78.359,95.885) 78.359,96.008 79.887,97.536 R3.2 ; v1(118.618,80.391) R5.2 ; v1(119.253,94.488) 113.665,94.488 R3.2 ; R6.1 113.792,103.886 110.617,100.711 R3.2
VCC_5V: C5.1 C6.2 C11.1 C13.2 R2.1 R4.1 R8.2 R9.2 R10.2 RES1.1 S5.1 SW1.3 U3.1 U4.1 U6.2 U6.18 U6.19 U7.38 U8.8 U9.3 | length 264.5
  Top Layer w0.254: SW1.3 45.466,71.016 C5.1 54.229,63.119 C6.2 R2.1 65.786,64.516 S5.1 ; v1(60.325,88.519) v1(60.325,95.885) ; U6.19 U6.18 67.818,108.585 105.918,108.585 U6.2 107.188,105.029 R4.1 ; C13.2 71.628,64.262 S5.1 ; v1(76.581,90.17) 81.026,90.17 C11.1 82.55,90.17 RES1.1 ; R10.2 80.772,49.53 S5.1 ; v1(90.678,84.201) 91.844,83.035 U7.38 ; U8.8 112.268,82.169 R8.2 R9.2 118.11,75.438 118.11,68.199 116.713,66.802 U3.1
  Bottom Layer w0.254: U4.1 41.275,50.927 41.275,58.928 C5.1 ; v1(60.325,88.519) 68.58,88.519 70.358,90.297 76.454,90.297 v1(76.581,90.17) 76.581,84.709 72.898,81.026 72.898,72.771 C13.2 ; v1(60.325,95.885) 64.008,99.568 U6.19 ; R10.2 U9.3 ; RES1.1 86.233,84.201 v1(90.678,84.201) 92.202,85.725 108.712,85.725 U8.8
VCC_IN: C1.1 C2.2 C8.1 SW1.2 U1.16 U2.3 USB.1 | length 59.6
  Top Layer w0.254: C1.1 53.594,96.393 56.896,93.091 ; USB.1 v1(56.896,89.281) 56.896,93.091 ; U1.16 64.862,103.505 C2.2 59.083,103.505 U2.3 56.416,98.778 C8.1 56.896,95.758 56.896,93.091
  Bottom Layer w0.254: SW1.2 56.896,80.446 v1(56.896,89.281)
XTAL1: C14.2 U7.15 Y3.1 | length 20.9
  Top Layer w0.254: v1@89.444,67.6 v1(89.444,67.818) U7.15 ; C14.2 96.139,56.769 Y3.1
  Bottom Layer w0.254: v1(89.444,67.818) 91.44,67.818 94.234,65.024 94.234,61.722 C14.2
XTAL2: C15.2 U7.14 Y3.2 | length 19.6
  Top Layer w0.254: C15.2 92.583,54.991 Y3.2 ; v1(88.392,69.215) 88.644,69.467 U7.14
  Bottom Layer w0.254: C15.2 86.614,60.96 86.614,65.278 88.392,67.056 v1(88.392,69.215)
pads on no net: S1.3 S1.4 S2.3 S2.4 S3.3 S3.4 S4.3 S4.4 S5.3 S5.4 SW1.1 SW1.4 SW1.5 SW1.6 SW2.1 SW2.4 SW2.5 SW2.6 U1.9 U1.10 U1.11 U1.12 U1.13 U1.14 U1.15 U2.4 U5.2 U5.4 U5.5 U5.6 U5.7 U5.8 U5.11 U5.13 U5.14 USB.5 USB.6

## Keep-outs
Keep-Out Layer:
  the board outline again, w0.013

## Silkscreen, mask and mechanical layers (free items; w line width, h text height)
Bottom Overlay:
  circle w0.013: c45,105 r2
  circle w0.013: c132,105 r2
  circle w0.013: c132,45 r2
  circle w0.013: c45,45 r2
